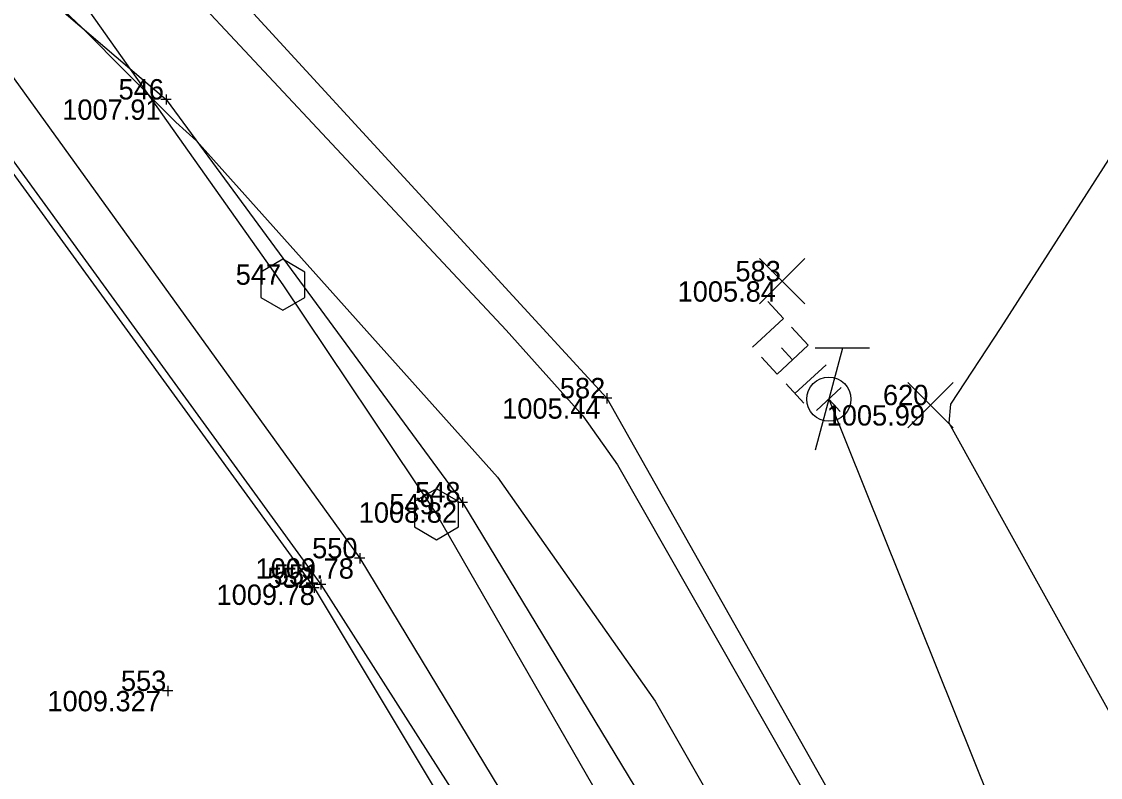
# Model space of a CAD drawing. Extents: x 2354693 to 2355622, y 637071 to 710080.
# Drawn here: x 2355298.3 to 2355361.9, y 709388.6 to 709433.1 of the extents above; entities that cross this region are included whole.
import ezdxf

# ---------------------------------------------------------------- set-up
doc = ezdxf.new("R2010")
doc.units = 0
for name, color, linetype in [('DT_X_Contour_Minor', 7, 'Continuous'), ('PM_X_Surveyed_Line', 7, 'Continuous'), ('PV_X_EOP', 7, 'Continuous'), ('PV_X_Shoulder', 7, 'Continuous'), ('RD_X_Cells', 7, 'Continuous'), ('RD_X_GR_Lt', 7, 'Continuous'), ('SV_X_Random_Point', 7, 'Continuous'), ('SV_X_Shot_Marker', 7, 'Continuous'), ('SV_X_Text_Elevation', 7, 'Continuous'), ('SV_X_Text_Name', 7, 'Continuous'), ('SV_X_Toe_of_Slope', 7, 'Continuous'), ('SV_X_Top_of_Bank', 7, 'Continuous'), ('UT_X_Telecom', 7, 'Continuous')]:
    doc.layers.add(name, color=color, linetype=linetype)

msp = doc.modelspace()

# ---------------------------------------------------------------- linework, layer by layer
at = {"layer": 'DT_X_Contour_Minor'}
for points in [[(2355344.218, 709493.664), (2355357.746, 709464.198), (2355360.105, 709448.427), (2355366.163, 709430.882), (2355356.052, 709415.121), (2355353.083, 709410.598), (2355352.991, 709409.493), (2355367.979, 709382.492)], [(2355344.218, 709493.664), (2355357.746, 709464.198), (2355360.105, 709448.427), (2355366.163, 709430.882), (2355356.052, 709415.121), (2355353.083, 709410.598), (2355352.991, 709409.493), (2355367.979, 709382.492)], [(2355256.514, 709490.43), (2355283.775, 709461.072), (2355292.628, 709451.208), (2355294.845, 709448.841), (2355297.747, 709446.107), (2355326.872, 709414.967), (2355331.388, 709409.92), (2355333.438, 709407.016), (2355350.907, 709376.422), (2355352.705, 709372.844), (2355354.66, 709368.362), (2355356.548, 709363.933), (2355356.786, 709361.932), (2355357.348, 709361.556), (2355357.12, 709361.279), (2355355.247, 709356.875), (2355352.274, 709351.479), (2355351.867, 709350.817), (2355351.589, 709350.682), (2355350.011, 709351.034), (2355346.353, 709350.204), (2355339.665, 709347.247)], [(2355256.514, 709490.43), (2355283.775, 709461.072), (2355292.628, 709451.208), (2355294.845, 709448.841), (2355297.747, 709446.107), (2355326.872, 709414.967), (2355331.388, 709409.92), (2355333.438, 709407.016), (2355350.907, 709376.422), (2355352.705, 709372.844), (2355354.66, 709368.362), (2355356.548, 709363.933), (2355356.786, 709361.932), (2355357.348, 709361.556), (2355357.12, 709361.279), (2355355.247, 709356.875), (2355352.274, 709351.479), (2355351.867, 709350.817), (2355351.589, 709350.682), (2355350.011, 709351.034), (2355346.353, 709350.204), (2355339.665, 709347.247)], [(2355255.69, 709482.934), (2355288.364, 709446.527), (2355296.545, 709437.792), (2355301.822, 709432.821), (2355307.383, 709427.211), (2355308.607, 709426.123), (2355326.354, 709406.292), (2355335.671, 709393.094), (2355342.795, 709380.617), (2355351.9, 709362.495), (2355353.976, 709357.738), (2355354.28, 709357.384), (2355355.423, 709358.007), (2355354.109, 709354.918), (2355352.326, 709351.683), (2355351.808, 709350.842), (2355351.641, 709350.76), (2355349.634, 709351.208), (2355344.985, 709350.153), (2355336.482, 709346.393)], [(2355255.69, 709482.934), (2355288.364, 709446.527), (2355296.545, 709437.792), (2355301.822, 709432.821), (2355307.383, 709427.211), (2355308.607, 709426.123), (2355326.354, 709406.292), (2355335.671, 709393.094), (2355342.795, 709380.617), (2355351.9, 709362.495), (2355353.976, 709357.738), (2355354.28, 709357.384), (2355355.423, 709358.007), (2355354.109, 709354.918), (2355352.326, 709351.683), (2355351.808, 709350.842), (2355351.641, 709350.76), (2355349.634, 709351.208), (2355344.985, 709350.153), (2355336.482, 709346.393)]]:
    msp.add_lwpolyline(points, dxfattribs=at)
at = {"layer": 'PM_X_Surveyed_Line'}
msp.add_lwpolyline([(2355180.148, 709561.237), (2355214.753, 709522.888), (2355249.307, 709484.271), (2355284.017, 709443.142), (2355315.552, 709399.77), (2355328.888, 709377.573), (2355342.967, 709349.789), (2355353.365, 709324.191), (2355361.351, 709299.648), (2355367.764, 709272.473), (2355372.191, 709243.487), (2355373.87, 709217.884), (2355371.213, 709164.414), (2355367.135, 709139.625), (2355360.061, 709111.877), (2355351.618, 709085.78), (2355342.505, 709062.338), (2355329.445, 709031.419), (2355320.624, 709012.583)], dxfattribs=at)
at = {"layer": 'PV_X_EOP'}
msp.add_lwpolyline([(2355180.814, 709561.741), (2355215.64, 709523.556), (2355249.922, 709484.356), (2355284.407, 709443.36), (2355315.939, 709399.966), (2355329.751, 709378.355), (2355343.524, 709350.098), (2355349.219, 709351.4), (2355359.304, 709326.795), (2355367.588, 709301.754), (2355374.108, 709275.907), (2355368.17, 709272.694), (2355372.498, 709243.563), (2355374.502, 709217.665), (2355371.414, 709164.432), (2355367.842, 709139.325), (2355361.02, 709111.642), (2355352.388, 709085.56), (2355343.445, 709061.967), (2355330.49, 709031.083), (2355321.141, 709011.801)], dxfattribs=at)
at = {"layer": 'PV_X_Shoulder'}
msp.add_lwpolyline([(2355182.191, 709563.218), (2355217.156, 709524.646), (2355251.587, 709486.128), (2355286.914, 709444.936), (2355318.238, 709401.514), (2355331.465, 709379.667), (2355345.367, 709350.943)], dxfattribs=at)
at = {"layer": 'RD_X_Cells'}
for points in [[(2355312.412, 709416.888), (2355313.711, 709416.138), (2355315.009, 709416.888), (2355315.009, 709418.388), (2355313.711, 709419.138), (2355312.412, 709418.388), (2355312.412, 709416.888)], [(2355321.46, 709403.362), (2355322.758, 709402.612), (2355324.056, 709403.362), (2355324.056, 709404.862), (2355322.758, 709405.612), (2355321.46, 709404.862), (2355321.46, 709403.362)]]:
    msp.add_lwpolyline(points, dxfattribs=at)
at = {"layer": 'RD_X_GR_Lt'}
msp.add_lwpolyline([(2355298.604, 709438.975), (2355313.711, 709417.638), (2355322.758, 709404.112), (2355335.403, 709382.171), (2355349.98, 709350.524)], dxfattribs=at)
at = {"layer": 'SV_X_Random_Point'}
for p, q in [((2355341.821, 709416.506), (2355344.488, 709419.176)), ((2355341.821, 709419.176), (2355344.488, 709416.506)), ((2355350.571, 709409.204), (2355353.237, 709411.874)), ((2355350.571, 709411.874), (2355353.237, 709409.204))]:
    msp.add_line(p, q, dxfattribs=at)
at = {"layer": 'SV_X_Shot_Marker'}
for p, q in [((2355306.813, 709428.859), (2355306.813, 709428.259)), ((2355307.113, 709428.559), (2355306.513, 709428.559)), ((2355332.808, 709411.244), (2355332.808, 709410.644)), ((2355333.108, 709410.944), (2355332.508, 709410.944)), ((2355324.599, 709404.811), (2355323.999, 709404.811)), ((2355324.299, 709405.111), (2355324.299, 709404.511)), ((2355318.538, 709401.514), (2355317.938, 709401.514)), ((2355318.238, 709401.814), (2355318.238, 709401.214)), ((2355315.939, 709400.266), (2355315.939, 709399.666)), ((2355315.852, 709399.77), (2355315.252, 709399.77)), ((2355315.552, 709400.07), (2355315.552, 709399.47)), ((2355316.239, 709399.966), (2355315.639, 709399.966)), ((2355306.913, 709393.996), (2355306.913, 709393.396)), ((2355307.213, 709393.696), (2355306.613, 709393.696))]:
    msp.add_line(p, q, dxfattribs=at)
at = {"layer": 'SV_X_Toe_of_Slope'}
msp.add_lwpolyline([(2355187.561, 709568.549), (2355223.434, 709529.363), (2355257.658, 709491.428), (2355294.213, 709452.947), (2355332.808, 709410.944), (2355352.903, 709375.39), (2355357.05, 709369.03), (2355359.176, 709363.173)], dxfattribs=at)
at = {"layer": 'SV_X_Top_of_Bank'}
msp.add_lwpolyline([(2355296.627, 709437.256), (2355306.813, 709428.559), (2355324.299, 709404.811), (2355337.209, 709383.506), (2355351.163, 709353.006)], dxfattribs=at)
at = {"layer": 'UT_X_Telecom'}
for p, q in [((2355346.708, 709413.895), (2355345.101, 709407.895)), ((2355348.308, 709413.895), (2355345.108, 709413.895)), ((2355346.639, 709411.573), (2355345.17, 709410.216)), ((2355345.904, 709410.895), (2355346.579, 709410.164)), ((2355345.904, 709410.895), (2355420.443, 709225.551))]:
    msp.add_line(p, q, dxfattribs=at)
for points in [[(2355341.394, 709413.95), (2355343.231, 709415.645), (2355342.31, 709416.643)], [(2355341.928, 709413.371), (2355342.85, 709412.373), (2355344.686, 709414.069), (2355343.698, 709415.139)], [(2355343.761, 709413.214), (2355343.107, 709413.923)], [(2355343.904, 709411.231), (2355345.741, 709412.927)], [(2355344.438, 709410.652), (2355343.383, 709411.795)]]:
    msp.add_lwpolyline(points, dxfattribs=at)
msp.add_circle((2355345.904, 709410.895), 1.3, dxfattribs=at)

# ---------------------------------------------------------------- texts
at = {"layer": 'SV_X_Text_Elevation'}
for s, p in [('1007.91', (2355300.692, 709427.359)), ('1005.84', (2355336.985, 709416.641)), ('1005.44', (2355326.638, 709409.744)), ('1005.99', (2355345.775, 709409.339)), ('1008.82', (2355318.18, 709403.611)), ('1009.78', (2355312.092, 709400.314)), ('1009.78', (2355309.792, 709398.766)), ('1009.327', (2355299.817, 709392.496))]:
    msp.add_text(s, height=1.2, dxfattribs=at).set_placement(p)
at = {"layer": 'SV_X_Text_Name'}
for s, p in [('546', (2355304.014, 709428.559)), ('547', (2355310.924, 709417.638)), ('583', (2355340.396, 709417.841)), ('582', (2355330.04, 709410.944)), ('620', (2355349.096, 709410.539)), ('548', (2355321.504, 709404.811)), ('549', (2355319.98, 709404.112)), ('550', (2355315.43, 709401.514)), ('552', (2355312.784, 709399.77)), ('551', (2355313.168, 709399.966)), ('553', (2355304.154, 709393.696))]:
    msp.add_text(s, height=1.2, dxfattribs=at).set_placement(p)

doc.saveas('drawing.dxf')
